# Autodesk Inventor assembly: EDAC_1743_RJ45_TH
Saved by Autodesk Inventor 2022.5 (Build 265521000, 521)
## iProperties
Created: 2024-12
Part Number: EDAC_1743_RJ45_TH
Document SubType Name: Assembly
Designer: AdminForWorker
Title: EDAC_1743_RJ45_TH v1
Author: AdminForWorker
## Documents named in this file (5)
- c:\worker\convert-fusion-r05-cosv3\tmp\job-1\35\temp\files\545dca92-a972-481a-9197-dd1a1176500e\EDAC_1743_RJ45_TH v1.iam
- c:\worker\convert-fusion-r05-cosv3\tmp\job-1\35\temp\files\545dca92-a972-481a-9197-dd1a1176500e\shell_1.ipt
- c:\worker\convert-fusion-r05-cosv3\tmp\job-1\35\temp\files\545dca92-a972-481a-9197-dd1a1176500e\wiring.iam
- c:\worker\convert-fusion-r05-cosv3\tmp\job-1\35\temp\files\545dca92-a972-481a-9197-dd1a1176500e\base_1.ipt
- c:\worker\convert-fusion-r05-cosv3\tmp\job-1\35\temp\files\545dca92-a972-481a-9197-dd1a1176500e\lights.iam
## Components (4 placed, 4 different names)
1. shell:1
2. wiring:1 [sub-assembly]
3. base:1
4. lights:1 [sub-assembly]
